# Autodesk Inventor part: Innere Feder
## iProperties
Created: 2009-04
Part Number: Innere Feder
Document SubType Name: Modeling
Designer: Hans-Jürgen Eicke
d400: 10,000 mm
Author: Hans-Jürgen Eicke
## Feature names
1. Extrusion1
2. Spirale2
